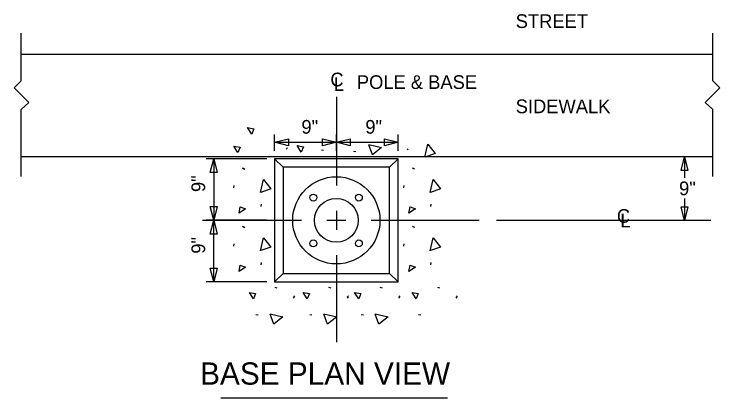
# Model space of a CAD drawing. Extents: x 10122.8 to 10170.2, y 10095.7 to 10157.1.
# Drawn here: x 10131.84 to 10166.16, y 10138.45 to 10157.12 of the extents above; entities that cross this region are included whole.
import ezdxf

# ---------------------------------------------------------------- set-up
doc = ezdxf.new("R2010")
doc.units = 0
for name, color, linetype in [('G-ANNO-TEXT', 7, 'Continuous'), ('G-DETL-LINE', 7, 'Continuous'), ('G-DETL-OTLN', 7, 'Continuous'), ('G-DETL-PATT', 7, 'Continuous')]:
    doc.layers.add(name, color=color, linetype=linetype)

msp = doc.modelspace()

# ---------------------------------------------------------------- linework, layer by layer
at = {"layer": 'G-ANNO-TEXT'}
for p, q in [((10132.179, 10153.884), (10132.179, 10156.194)), ((10165.817, 10153.884), (10165.817, 10156.194)), ((10132.179, 10153.884), (10131.835, 10153.54)), ((10165.817, 10153.884), (10166.161, 10153.54)), ((10131.835, 10153.54), (10132.545, 10152.829)), ((10166.161, 10153.54), (10165.451, 10152.829)), ((10132.545, 10152.829), (10132.179, 10152.477)), ((10147.507, 10153.1), (10147.507, 10148.788)), ((10165.451, 10152.829), (10165.817, 10152.477)), ((10132.179, 10149.22), (10132.179, 10152.477)), ((10165.817, 10149.22), (10165.817, 10152.477)), ((10144.507, 10150.463), (10144.507, 10151.263)), ((10147.507, 10150.463), (10147.507, 10151.263)), ((10150.507, 10150.463), (10150.507, 10151.263)), ((10144.507, 10150.888), (10147.507, 10150.888)), ((10147.507, 10150.888), (10150.507, 10150.888)), ((10144.132, 10150.088), (10141.168, 10150.088)), ((10141.543, 10150.088), (10141.543, 10148.777)), ((10141.543, 10150.088), (10141.543, 10147.088)), ((10164.437, 10150.182), (10164.437, 10149.158)), ((10164.437, 10148.15), (10164.437, 10147.086)), ((10147.507, 10147.547), (10147.507, 10146.628)), ((10140.993, 10147.088), (10145.807, 10147.088)), ((10144.132, 10147.088), (10141.168, 10147.088)), ((10141.543, 10144.088), (10141.543, 10147.088)), ((10147.048, 10147.088), (10147.967, 10147.088)), ((10149.207, 10147.088), (10154.451, 10147.088)), ((10165.718, 10147.086), (10155.297, 10147.086)), ((10147.507, 10145.388), (10147.507, 10141.167)), ((10144.132, 10144.088), (10141.168, 10144.088)), ((10141.881, 10138.448), (10152.916, 10138.448))]:
    msp.add_line(p, q, dxfattribs=at)
for points in [[(10145.174, 10150.721), (10144.507, 10150.888), (10145.174, 10151.054)], [(10146.841, 10151.054), (10147.507, 10150.888), (10146.841, 10150.721)], [(10148.174, 10150.721), (10147.507, 10150.888), (10148.174, 10151.054)], [(10149.841, 10151.054), (10150.507, 10150.888), (10149.841, 10150.721)], [(10141.376, 10149.421), (10141.543, 10150.088), (10141.71, 10149.421)], [(10164.27, 10149.515), (10164.437, 10150.182), (10164.604, 10149.515)], [(10141.71, 10147.754), (10141.543, 10147.088), (10141.376, 10147.754)], [(10164.604, 10147.752), (10164.437, 10147.086), (10164.27, 10147.752)], [(10141.376, 10146.421), (10141.543, 10147.088), (10141.71, 10146.421)], [(10141.71, 10144.754), (10141.543, 10144.088), (10141.376, 10144.754)]]:
    msp.add_lwpolyline(points, close=True, dxfattribs=at)
at = {"layer": 'G-DETL-LINE'}
for p, q in [((10132.179, 10155.168), (10165.82, 10155.168)), ((10132.179, 10150.195), (10165.82, 10150.195)), ((10144.507, 10150.088), (10144.919, 10149.677)), ((10150.095, 10149.677), (10150.507, 10150.088)), ((10144.507, 10144.088), (10144.919, 10144.5)), ((10150.095, 10144.5), (10150.507, 10144.088))]:
    msp.add_line(p, q, dxfattribs=at)
msp.add_circle((10147.507, 10147.088), 1.06, dxfattribs=at)
at = {"layer": 'G-DETL-OTLN'}
for p, q in [((10150.507, 10150.088), (10144.507, 10150.088)), ((10144.507, 10150.088), (10144.507, 10144.088)), ((10150.507, 10144.088), (10150.507, 10150.088)), ((10150.095, 10149.677), (10144.919, 10149.677)), ((10144.919, 10149.677), (10144.919, 10144.5)), ((10150.095, 10144.5), (10150.095, 10149.677)), ((10144.919, 10144.5), (10150.095, 10144.5)), ((10144.507, 10144.088), (10150.507, 10144.088))]:
    msp.add_line(p, q, dxfattribs=at)
for centre, radius in [((10147.507, 10147.088), 2.12), ((10146.386, 10148.193), 0.167), ((10148.603, 10148.193), 0.167), ((10146.386, 10145.967), 0.167), ((10148.603, 10145.967), 0.167)]:
    msp.add_circle(centre, radius, dxfattribs=at)
at = {"layer": 'G-DETL-PATT'}
for p, q in [((10145.125, 10150.61), (10145.072, 10150.55)), ((10146.778, 10150.512), (10146.886, 10150.495)), ((10148.349, 10150.457), (10148.457, 10150.44)), ((10150.944, 10150.567), (10151.004, 10150.514)), ((10142.945, 10149.64), (10143.005, 10149.587)), ((10142.995, 10149.627), (10143.055, 10149.574)), ((10151.206, 10149.64), (10151.266, 10149.587)), ((10151.255, 10149.627), (10151.316, 10149.574)), ((10142.525, 10148.675), (10142.542, 10148.783)), ((10150.786, 10148.675), (10150.803, 10148.783)), ((10143.848, 10147.76), (10143.865, 10147.868)), ((10152.109, 10147.76), (10152.126, 10147.868)), ((10142.945, 10146.802), (10143.005, 10146.749)), ((10142.995, 10146.789), (10143.055, 10146.737)), ((10151.206, 10146.802), (10151.266, 10146.749)), ((10151.255, 10146.789), (10151.316, 10146.737)), ((10142.525, 10145.838), (10142.542, 10145.946)), ((10150.786, 10145.838), (10150.803, 10145.946)), ((10143.848, 10144.923), (10143.865, 10145.031)), ((10152.109, 10144.923), (10152.126, 10145.031)), ((10144.51, 10143.828), (10144.618, 10143.811)), ((10147.127, 10143.828), (10147.235, 10143.811)), ((10149.629, 10143.828), (10149.737, 10143.811)), ((10152.421, 10143.828), (10152.529, 10143.811)), ((10145.461, 10143.359), (10145.408, 10143.299)), ((10145.474, 10143.408), (10145.421, 10143.348)), ((10148.079, 10143.359), (10148.026, 10143.299)), ((10148.092, 10143.408), (10148.039, 10143.348)), ((10150.58, 10143.359), (10150.528, 10143.299)), ((10150.593, 10143.408), (10150.54, 10143.348)), ((10153.373, 10143.359), (10153.32, 10143.299)), ((10153.386, 10143.408), (10153.333, 10143.348)), ((10143.594, 10142.505), (10143.702, 10142.488)), ((10146.212, 10142.505), (10146.32, 10142.488)), ((10148.714, 10142.505), (10148.822, 10142.488)), ((10151.506, 10142.505), (10151.614, 10142.488))]:
    msp.add_line(p, q, dxfattribs=at)
for points in [[(10143.191, 10151.599), (10143.493, 10151.542), (10143.39, 10151.285), (10143.191, 10151.599)], [(10149.08, 10150.776), (10149.705, 10150.633), (10149.261, 10150.273), (10149.083, 10150.765)], [(10151.816, 10150.165), (10151.958, 10150.79), (10152.319, 10150.346), (10151.826, 10150.168)], [(10142.522, 10150.699), (10142.824, 10150.642), (10142.721, 10150.384), (10142.522, 10150.699)], [(10145.605, 10150.726), (10145.907, 10150.669), (10145.804, 10150.412), (10145.605, 10150.726)], [(10143.816, 10148.447), (10143.959, 10149.071), (10144.32, 10148.627), (10143.827, 10148.45)], [(10152.077, 10148.447), (10152.22, 10149.071), (10152.58, 10148.627), (10152.088, 10148.45)], [(10142.775, 10147.444), (10142.832, 10147.746), (10143.089, 10147.643), (10142.775, 10147.444)], [(10151.036, 10147.444), (10151.093, 10147.746), (10151.35, 10147.643), (10151.036, 10147.444)], [(10143.816, 10145.609), (10143.959, 10146.234), (10144.32, 10145.79), (10143.827, 10145.612)], [(10152.077, 10145.609), (10152.22, 10146.234), (10152.58, 10145.79), (10152.088, 10145.612)], [(10142.775, 10144.606), (10142.832, 10144.909), (10143.089, 10144.805), (10142.775, 10144.606)], [(10151.036, 10144.606), (10151.093, 10144.909), (10151.35, 10144.805), (10151.036, 10144.606)], [(10143.278, 10143.578), (10143.58, 10143.521), (10143.477, 10143.264), (10143.278, 10143.578)], [(10145.896, 10143.578), (10146.198, 10143.521), (10146.095, 10143.264), (10145.896, 10143.578)], [(10148.397, 10143.578), (10148.7, 10143.521), (10148.596, 10143.264), (10148.397, 10143.578)], [(10151.19, 10143.578), (10151.492, 10143.521), (10151.389, 10143.264), (10151.19, 10143.578)], [(10144.281, 10142.537), (10144.905, 10142.394), (10144.462, 10142.034), (10144.284, 10142.526)], [(10146.899, 10142.537), (10147.523, 10142.394), (10147.08, 10142.034), (10146.902, 10142.526)], [(10149.4, 10142.537), (10150.025, 10142.394), (10149.581, 10142.034), (10149.403, 10142.526)]]:
    msp.add_lwpolyline(points, dxfattribs=at)

# ---------------------------------------------------------------- texts
at = {"layer": 'G-ANNO-TEXT'}
for s, height, p in [('STREET', 0.6667, (10156.229, 10156.447)), ('C', 0.667, (10147.216, 10153.607)), ('L', 0.667, (10147.383, 10153.384)), ('POLE & BASE', 0.66667, (10148.505, 10153.481)), ('SIDEWALK', 0.6667, (10156.229, 10152.301)), ('9"', 0.6667, (10145.809, 10151.304)), ('9"', 0.6667, (10148.916, 10151.304)), ('9"', 0.6667, (10164.176, 10148.311)), ('C', 0.667, (10161.152, 10146.967)), ('L', 0.667, (10161.318, 10146.744)), ('BASE PLAN VIEW', 1.08333, (10140.881, 10139.091))]:
    msp.add_text(s, height=height, dxfattribs=at).set_placement(p)
for p in [(10141.126, 10148.464), (10141.126, 10145.464)]:
    msp.add_text('9"', height=0.6667, rotation=90, dxfattribs=at).set_placement(p)

doc.saveas('drawing.dxf')
